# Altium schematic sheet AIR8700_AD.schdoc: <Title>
size 419 x 266 mm; Name: SIZEB; Symbol: SIZEB; Device: SIZEB; Drawn By: <Drawn By>; Checked By: <Checked By>; QC By: <QC By>; Released By: <Released By>; Drawn Date: <Drawn Date>; Checked Date: <Checked Date>; QC Date: <QC Date>; Release Date: <Release Date>; Company Name: <Company Name>; Code: <Code>; Sheet Size: B; Drawing Number: <Drawing Number>; Revision: <Revision>; Scale: <Scale>; Sheet Number: 1; Number of Sheets: 1; @Page No: 1; @Page Count: 1; @Schematic Name: _AIR8700-PADS; @Project Name: AIR8700-PADS; @Board Name: _AIR8700-PADS; @Update Date: 2026-06-29; @Create Time: 07:46:41; @Update Time: 15:46:41; @Page Name: sheet1; @Create Date: 2026-06-29
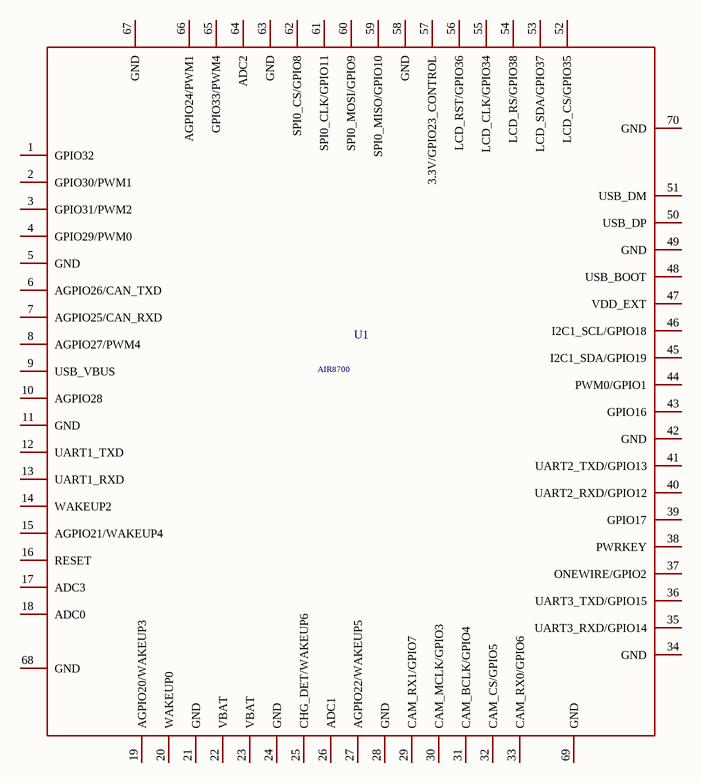
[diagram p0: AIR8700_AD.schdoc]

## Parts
U1  PART-TYPE: AIR8700  (hidden comment: AIR8700-PADS)

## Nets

Not connected (* = marked no-connect by the designer): U1 1(GPIO32) 2(GPIO30/PWM1) 3(GPIO31/PWM2) 4(GPIO29/PWM0) 5(GND) 6(AGPIO26/CAN_TXD) 7(AGPIO25/CAN_RXD) 8(AGPIO27/PWM4) 9(USB_VBUS) 10(AGPIO28) 11(GND) 12(UART1_TXD) 13(UART1_RXD) 14(WAKEUP2) 15(AGPIO21/WAKEUP4) 16(RESET) 17(ADC3) 18(ADC0) 19(AGPIO20/WAKEUP3) 20(WAKEUP0) 21(GND) 22(VBAT) 23(VBAT) 24(GND) 25(CHG_DET/WAKEUP6) 26(ADC1) 27(AGPIO22/WAKEUP5) 28(GND) 29(CAM_RX1/GPIO7) 30(CAM_MCLK/GPIO3) 31(CAM_BCLK/GPIO4) 32(CAM_CS/GPIO5) 33(CAM_RX0/GPIO6) 34(GND) 35(UART3_RXD/GPIO14) 36(UART3_TXD/GPIO15) 37(ONEWIRE/GPIO2) 38(PWRKEY) 39(GPIO17) 40(UART2_RXD/GPIO12) 41(UART2_TXD/GPIO13) 42(GND) 43(GPIO16) 44(PWM0/GPIO1) 45(I2C1_SDA/GPIO19) 46(I2C1_SCL/GPIO18) 47(VDD_EXT) 48(USB_BOOT) 49(GND) 50(USB_DP) 51(USB_DM) 52(LCD_CS/GPIO35) 53(LCD_SDA/GPIO37) 54(LCD_RS/GPIO38) 55(LCD_CLK/GPIO34) 56(LCD_RST/GPIO36) 57(3.3V/GPIO23_CONTROL) 58(GND) 59(SPI0_MISO/GPIO10) 60(SPI0_MOSI/GPIO9) 61(SPI0_CLK/GPIO11) 62(SPI0_CS/GPIO8) 63(GND) 64(ADC2) 65(GPIO33/PWM4) 66(AGPIO24/PWM1) 67(GND) 68(GND) 69(GND) 70(GND)

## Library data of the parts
U1 = AIR8700-PADS: Add into BOM: yes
